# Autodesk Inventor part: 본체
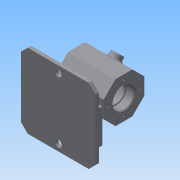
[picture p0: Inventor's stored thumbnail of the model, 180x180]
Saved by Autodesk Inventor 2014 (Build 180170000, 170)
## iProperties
Created: 2018-06
Part Number: 본체
Material: 일반
Document SubType Name: Modeling
Designer: net
Density: 1 g/cm^3
Appearance: 기본값
Mass: 204.441 g
Surface Area: 601.93 cm^2
Volume: 204.441 cm^3
Author: net
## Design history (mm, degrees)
sketch "스케치1" dims "d0" = 60
  geometry: L1 (30, -12.426)-(12.426, -30); L2 (12.426, -30)-(-12.426, -30); L3 (-12.426, -30)-(-30, -12.426); L4 (-30, -12.426)-(-30, 12.426); L5 (-30, 12.426)-(-12.426, 30); L6 (-12.426, 30)-(12.426, 30); L7 (12.426, 30)-(30, 12.426); L8 (30, 12.426)-(30, -12.426); 4 further points
  constraints: 16 end point, 2 coincident, 1 horizontal, 1 horizontal alignment, 1 midpoint, 19 other
extrude "돌출1" new body sketch "스케치1" stored distance "d1" = 70; taper "d2" = 0 deg
sketch "스케치2"
  geometry: L1 (-35, 0)-(35, 0); L2 (-35, 0)-(-35, 16); L3 (-35, 16)-(-23, 16); L4 (-23, 16)-(-23, 14); L5 (-23, 14)-(-20, 14); L6 (-20, 14)-(-20, 25); L7 (-20, 25)-(20, 25); L8 (20, 25)-(20, 14); L9 (20, 14)-(23, 14); L10 (23, 14)-(23, 16); L11 (23, 16)-(35, 16); L12 (35, 16)-(35, 0); 1 further point
  constraints: 24 end point, 9 parallel, 3 perpendicular, 1 collinear, 1 horizontal
  dimensions: "d3" = 70 distance of L1.start L1.end; "d4" = 0 distance from line of point (0, 0) L1; "d5" = 35 distance of point (0, 0) L1.end; "d6" = 16 distance of L1.start L2.end; "d7" = 12 distance of L2.end L3.end; "d8" = 2 distance of L3.end L4.end; "d9" = 3 distance of L4.end L5.end; "d10" = 11 distance of L5.end L6.end; "d11" = 40 distance of L6.end L7.end; "d12" = 3 distance of L8.end L9.end
revolve "회전1" sketch "스케치2" stored, may be unused: angle "d13" = 90 deg
sketch "스케치3"
  geometry: L1 (0, 0)-(26.163, 26.163); L2 (12.426, 30)-(30, 12.426) reference; L3 (0, 0)-(34.472, 0); L4 (26.163, 26.163)-(20.506, 31.82); L5 (20.506, 31.82)-(15.556, 26.87); L6 (21.213, 21.213)-(15.556, 26.87); L7 (21.213, 21.213)-(26.163, 26.163); L8 (18.385, 24.042)-(23.335, 28.991)
  constraints: 14 end point, 3 midpoint, 1 collinear, 1 horizontal, 1 parallel, 1 perpendicular, 1 point on line
  dimensions: "d14" = 7 distance from line of L2 L1.end; "d15" = 45 deg angle of L3 L1; "d16" = 8 distance of L1.end L4.end
revolve "회전2" sketch "스케치3" stored, may be unused: angle "d17" = 90 deg
sketch "스케치4"
  geometry: C1 r 4 at (0, 0) reference
extrude "돌출2" cut sketch "스케치4" distance "d18" = 30; taper "d19" = 0 deg
node "작업 평면1"
sketch "스케치5"
  geometry: L1 (-20, 67.426)-(90, 67.426); L2 (90, 67.426)-(90, -42.574); L3 (90, -42.574)-(-20, -42.574); L4 (-20, -42.574)-(-20, 67.426); C1 r 5 at (35, 57.426); C2 r 5 at (35, -32.574); 1 further point
  constraints: 8 end point, 2 centre point, 2 parallel, 2 perpendicular, 1 horizontal, 1 vertical alignment
  dimensions: "d21" = 110 distance of L2.end L3.end; "d22" = 55 distance from line of L2 point (35, 12.426); "d23" = 55 distance from line of point (35, 12.426) L1; "d24" = 10 diameter of C1; "d25" = 10 diameter of C2; "d26" = 10 distance from line of L1 C1.centre; "d27" = 10 distance from line of L3 C2.centre; "d28" = 55 distance from line of L2 C1.centre
extrude "돌출3" join sketch "스케치5" distance "d29" = 5; taper "d30" = 0 deg
sketch "스케치6"
  geometry: L1 (90, 67.426)-(-20, 67.426) reference; L2 (-20, 67.426)-(-20, -42.574) reference; L3 (-20, -42.574)-(90, -42.574) reference; L4 (90, -42.574)-(90, 67.426) reference; L5 (-20, 37.426)-(90, 37.426); L6 (90, 37.426)-(90, -12.574); L7 (90, -12.574)-(-20, -12.574); L8 (-20, -12.574)-(-20, 37.426); 1 further point
  constraints: 8 end point, 2 parallel, 2 point on line, 1 horizontal, 1 perpendicular
  dimensions: "d31" = 30 distance between parallel lines of L1 L5; "d32" = 30 distance between parallel lines of L3 L7
extrude "돌출4" join sketch "스케치6" distance "d33" = 5; taper "d34" = 0 deg
sketch "스케치7"
  geometry: L1 (-20, -12.574)-(90, -12.574) reference; L2 (90, -12.574)-(90, 37.426) reference; L3 (16, 12.426)-(54, 12.426); L4 (16, 7.426)-(54, 7.426); L5 (54, 17.426)-(16, 17.426); L6 (90, 67.426)-(-20, 67.426) reference; A1 r 5 centre (16, 12.426) between (16, 17.426) and (16, 7.426); A2 r 5 centre (54, 12.426) between (54, 7.426) and (54, 17.426); 2 further points
  constraints: 8 end point, 4 point on circle, 4 tangent, 2 centre point, 2 parallel, 1 midpoint
  dimensions: "d35" = 38 distance of L3.start L3.end; "d36" = 10 diameter of A2; "d37" = 55 distance from line of L6 point (35, 12.426); "d38" = 55 distance from line of L2 point (35, 12.426)
extrude "돌출5" join sketch "스케치7" stored distance "d39" = 5; taper "d40" = 0 deg
sketch "스케치8"
  geometry: C1 r 16 at (0, 0) reference; 4 further points
  constraints: 1 vertical alignment, 5 other
  dimensions: "d41" = 23 distance of C1.centre point (0, 23); "d44" = 360 deg dimension on C1.centre point (0, 23) (derived)
hole "구멍1" sketch "스케치8" at (0, 23), (-23, 0), (0, -23), (23, 0) diameter "d46" = 3.242; stored, may be unused: countersink angle "d50" = 90 deg, drill point angle "d52" = 118 deg; dims "d47" = 8, "d48" = 4, "d49" = 2, "d51" = 10
chamfer "모따기1" distance "d53" = 10; stored, may be unused: second distance "d54" = 2, angle "d55" = 45 deg
chamfer "모따기2" distance "d56" = 1; stored, may be unused: second distance "d57" = 2, angle "d58" = 45 deg
sketch "스케치9"
  geometry: L1 (0, 0)-(0, 24.853) reference; L2 (70, 42.426)-(0, 42.426) reference; 2 further points
  constraints: 1 other
  dimensions: "d60" = 30 distance from line of L2 point (35, 12.426); "d61" = 35 distance from line of L1 point (35, 12.426)
feature "엠보싱1" sketch "스케치9" dims "d0" = 60, "d3" = 70, "d4" = 0, "d5" = 35, "d6" = 16, "d7" = 12, "d8" = 2, "d9" = 3, "d10" = 11, "d11" = 40, "d12" = 3, "d62" = 0.5, "d63" = 0
fillet "모깎기1" dims "d64" = 1, "d65" = 2, "d66" = 3, "d67" = 0.3
node "솔리드1"
mirror "대칭1"
other parameters: "d20" = -92
